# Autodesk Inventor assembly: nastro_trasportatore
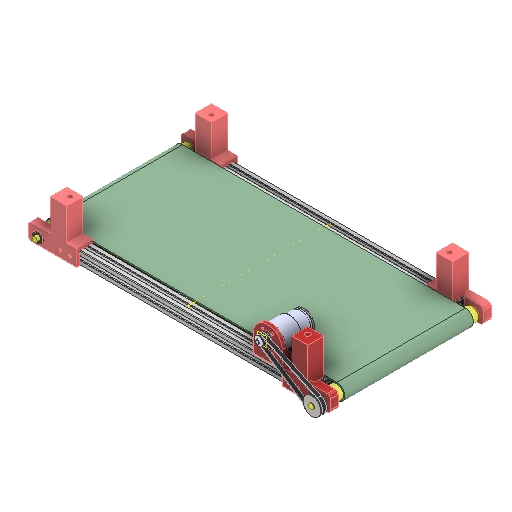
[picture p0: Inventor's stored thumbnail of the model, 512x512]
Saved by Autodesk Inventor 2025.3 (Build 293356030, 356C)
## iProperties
Created: 2025-05
Part Number: nastro_trasportatore
Document SubType Name: Assembly
Designer: R5800u
Author: R5800u
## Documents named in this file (20)
- C:\Users\R5800u\Desktop\nastro_trasportatore_02\nastro_trasportatore.iam
- C:\Users\R5800u\Desktop\nastro_trasportatore_02\tslot-20x20-1.ipt
- C:\Users\R5800u\Desktop\nastro_trasportatore_02\tslot-20x20-1_MIR.ipt
- C:\Users\R5800u\Desktop\nastro_trasportatore_02\tslot-20x20-2.ipt
- C:\Users\R5800u\Desktop\nastro_trasportatore_02\SNSD20x20.ipt
- C:\Users\R5800u\Desktop\nastro_trasportatore_02\SNSD20x20_MIR.ipt
- C:\Users\R5800u\Desktop\nastro_trasportatore_02\MM-JGB37 v4_MIR_MIR.ipt
- C:\Users\R5800u\Desktop\nastro_trasportatore_02\JGB37-520_MIR_MIR.ipt
- C:\Users\R5800u\Desktop\nastro_trasportatore_02\lato.ipt
- C:\Users\R5800u\Desktop\nastro_trasportatore_02\cilindro_01.ipt
- C:\Users\R5800u\Desktop\nastro_trasportatore_02\piastra_laterale_cilindro.ipt
- C:\Users\R5800u\Desktop\nastro_trasportatore_02\GT2 Timing Pulley T40 small.ipt
- C:\Users\R5800u\Desktop\nastro_trasportatore_02\GT2 16 Teeth Free Pulley.ipt
- C:\Users\R5800u\Documents\Inventor\Content Center Files\R2025\it-IT\BS 290 SKF(30)\BS 290 SKF - SKF 618_8.ipt
- C:\Users\R5800u\Desktop\nastro_trasportatore_02\piastra_laterale_cilindro_MIR.ipt
- C:\Users\R5800u\Desktop\nastro_trasportatore_02\piastra_laterale_cilindro_MIR1.ipt
- C:\Users\R5800u\Desktop\nastro_trasportatore_02\piastra_laterale_cilindro_MIR_MIR.ipt
- C:\Users\R5800u\Desktop\nastro_trasportatore_02\cilindro_02.ipt
- C:\Users\R5800u\Desktop\nastro_trasportatore_02\cinghia.ipt
- C:\Users\R5800u\Desktop\nastro_trasportatore_02\nastro.ipt
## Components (30 placed, 19 different names)
1. tslot-20x20-1:1
2. tslot-20x20-1_MIR:1
3. tslot-20x20-2:1
4. tslot-20x20-2:2
5. SNSD20x20:1 — Allineato:14, Coincidente:22, Coincidente:23
6. SNSD20x20:2 — Allineato:13, Coincidente:20, Coincidente:21
7. SNSD20x20_MIR:1 — Allineato:15, Coincidente:24, Coincidente:27
8. SNSD20x20_MIR:2 — Allineato:16, Coincidente:25, Coincidente:26
9. tslot-20x20-2:3 — Allineato:17, Coincidente:28, Allineato:30, Allineato:32, Coincidente:30, Allineato:33, Coincidente:31
10. SNSD20x20_MIR:3 — Allineato:32, Coincidente:29, Coincidente:30
11. SNSD20x20:3 — Allineato:33, Coincidente:31, Coincidente:32
12. MM-JGB37 v4_MIR_MIR:1 — Coincidente:54, Coincidente:55, Rotazionale:5, Coincidente:68, Allineato:55, Allineato:56
13. JGB37-520_MIR_MIR:1 — Coincidente:54, Coincidente:55, Rotazionale:5, Rotazionale:6
14. lato:1
15. cilindro_01:1 — Coincidente:69, Coincidente:70, Coincidente:71, Coincidente:73, Coincidente:76, Allineato:67
16. piastra_laterale_cilindro:1 — Coincidente:72, Allineato:64
17. GT2 16 Teeth Free Pulley:1 — Rotazionale:6, Coincidente:74
18. GT2 Timing Pulley T40 small:1 — Coincidente:73, Coincidente:74, Allineato:66
19. BS 290 SKF 618/8:1 — Allineato:64, Coincidente:77
20. BS 290 SKF 618/8:2 — Coincidente:76, Coincidente:77
21. piastra_laterale_cilindro_MIR:1 — Rotazionale:7
22. BS 290 SKF 618/8:3 — Rotazionale:8
23. BS 290 SKF 618/8:4 — Rotazionale:7, Rotazionale:8
24. cilindro_02:1
25. piastra_laterale_cilindro_MIR1:1 — Allineato:65
26. BS 290 SKF 618/8:5 — Allineato:65
27. piastra_laterale_cilindro_MIR_MIR:1 — Rotazionale:9
28. BS 290 SKF 618/8:6 — Rotazionale:9
29. cinghia:1 — Allineato:66
30. nastro:1 — Allineato:67
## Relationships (43: Mate 24, Flush 14, RevoluteJoint 5)
- Allineato:13 [Flush]: SNSD20x20:2
- Coincidente:20 [Mate]: SNSD20x20:2
- Coincidente:21 [Mate]: SNSD20x20:2
- Allineato:14 [Flush]: SNSD20x20:1
- Coincidente:22 [Mate]: SNSD20x20:1
- Coincidente:23 [Mate]: SNSD20x20:1
- Allineato:15 [Flush]: SNSD20x20_MIR:1
- Allineato:16 [Flush]: SNSD20x20_MIR:2
- Coincidente:24 [Mate]: SNSD20x20_MIR:1
- Coincidente:25 [Mate]: SNSD20x20_MIR:2
- Coincidente:26 [Mate]: SNSD20x20_MIR:2
- Coincidente:27 [Mate]: SNSD20x20_MIR:1
- Allineato:17 [Flush]: tslot-20x20-2:3
- Coincidente:28 [Mate]: tslot-20x20-2:3
- Allineato:30 [Flush]: tslot-20x20-2:3
- Allineato:32 [Flush]: tslot-20x20-2:3 ↔ SNSD20x20_MIR:3
- Coincidente:29 [Mate]: SNSD20x20_MIR:3
- Coincidente:30 [Mate]: tslot-20x20-2:3 ↔ SNSD20x20_MIR:3
- Allineato:33 [Flush]: tslot-20x20-2:3 ↔ SNSD20x20:3
- Coincidente:31 [Mate]: tslot-20x20-2:3 ↔ SNSD20x20:3
- Coincidente:32 [Mate]: SNSD20x20:3
- Coincidente:54 [Mate]: MM-JGB37 v4_MIR_MIR:1 ↔ JGB37-520_MIR_MIR:1
- Coincidente:55 [Mate]: MM-JGB37 v4_MIR_MIR:1 ↔ JGB37-520_MIR_MIR:1
- Rotazionale:5 [RevoluteJoint]: MM-JGB37 v4_MIR_MIR:1 ↔ JGB37-520_MIR_MIR:1
- Coincidente:68 [Mate]: MM-JGB37 v4_MIR_MIR:1
- Allineato:55 [Flush]: MM-JGB37 v4_MIR_MIR:1
- Allineato:56 [Flush]: MM-JGB37 v4_MIR_MIR:1
- Coincidente:69 [Mate]: cilindro_01:1
- Coincidente:70 [Mate]: cilindro_01:1
- Coincidente:71 [Mate]: cilindro_01:1
- Coincidente:72 [Mate]: piastra_laterale_cilindro:1
- Rotazionale:6 [RevoluteJoint]: JGB37-520_MIR_MIR:1 ↔ GT2 16 Teeth Free Pulley:1
- Coincidente:73 [Mate]: cilindro_01:1 ↔ GT2 Timing Pulley T40 small:1
- Coincidente:74 [Mate]: GT2 16 Teeth Free Pulley:1 ↔ GT2 Timing Pulley T40 small:1
- Allineato:64 [Flush]: piastra_laterale_cilindro:1 ↔ BS 290 SKF 618/8:1
- Coincidente:76 [Mate]: cilindro_01:1 ↔ BS 290 SKF 618/8:2
- Coincidente:77 [Mate]: BS 290 SKF 618/8:1 ↔ BS 290 SKF 618/8:2
- Rotazionale:7 [RevoluteJoint]: piastra_laterale_cilindro_MIR:1 ↔ BS 290 SKF 618/8:4
- Rotazionale:8 [RevoluteJoint]: BS 290 SKF 618/8:3 ↔ BS 290 SKF 618/8:4
- Allineato:65 [Flush]: piastra_laterale_cilindro_MIR1:1 ↔ BS 290 SKF 618/8:5
- Rotazionale:9 [RevoluteJoint]: piastra_laterale_cilindro_MIR_MIR:1 ↔ BS 290 SKF 618/8:6
- Allineato:66 [Flush]: GT2 Timing Pulley T40 small:1 ↔ cinghia:1
- Allineato:67 [Flush]: cilindro_01:1 ↔ nastro:1
## Named parameters: d358_d357 = 0
